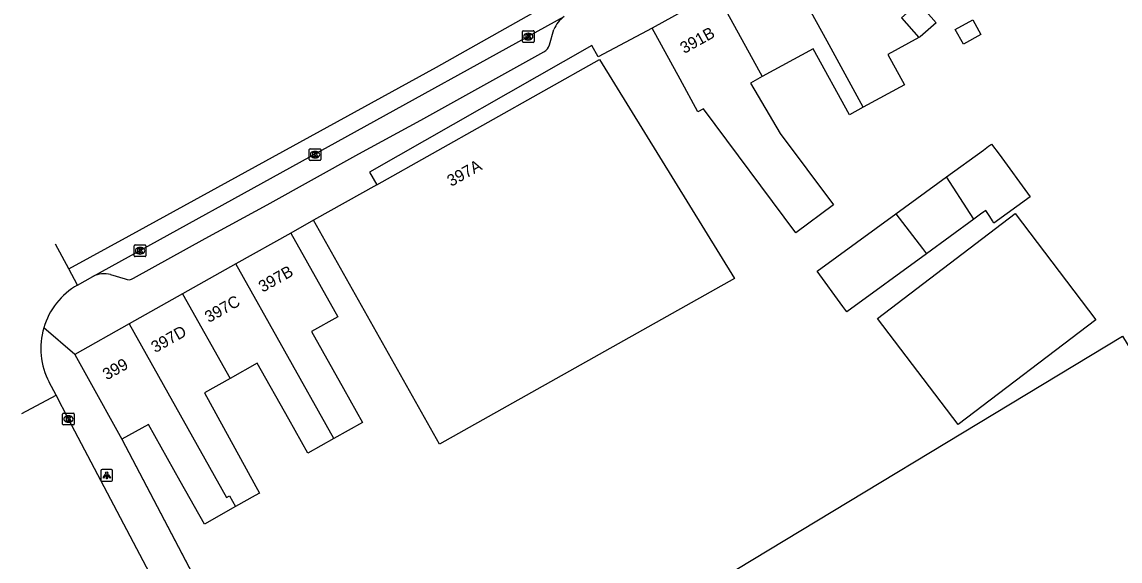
# Model space of a CAD drawing. Extents: x 159822 to 160765, y 380693 to 381634.
# Drawn here: x 159821.7 to 159915.8, y 381400.1 to 381446.3 of the extents above; entities that cross this region are included whole.
import ezdxf

# ---------------------------------------------------------------- set-up
doc = ezdxf.new("R2010")
doc.units = 0
for name, color, linetype in [('IMGEO_Kolk', 7, 'Continuous'), ('IMGEO_Lichtpunt', 7, 'Continuous'), ('IMGEO_Muur', 7, 'Continuous'), ('IMGEO_Pand', 7, 'Continuous'), ('IMGEO_Pand_nummerreeks', 7, 'Continuous'), ('IMGEO_Rijbaan_lokaal_gesloten', 7, 'Continuous'), ('IMGEO_Rijbaan_lokaal_open', 7, 'Continuous'), ('IMGEO_Voetpad_open', 7, 'Continuous')]:
    doc.layers.add(name, color=color, linetype=linetype)

msp = doc.modelspace()

# ---------------------------------------------------------------- linework, layer by layer
at = {"layer": 'IMGEO_Kolk'}
for p, q in [((159864.611, 381444.58), (159864.611, 381445.432)), ((159864.686, 381445.506), (159865.538, 381445.506)), ((159865.099, 381445.286), (159865.124, 381445.286)), ((159865.612, 381445.432), (159865.612, 381444.58)), ((159865.538, 381444.506), (159864.686, 381444.506)), ((159865.122, 381444.726), (159865.097, 381444.726)), ((159846.345, 381434.465), (159846.345, 381435.317)), ((159846.42, 381435.391), (159847.272, 381435.391)), ((159846.833, 381435.171), (159846.858, 381435.171)), ((159847.346, 381435.317), (159847.346, 381434.465)), ((159847.272, 381434.391), (159846.42, 381434.391)), ((159846.856, 381434.611), (159846.831, 381434.611)), ((159831.425, 381427.153), (159832.277, 381427.153)), ((159831.35, 381426.227), (159831.35, 381427.079)), ((159831.861, 381426.373), (159831.836, 381426.373)), ((159831.838, 381426.933), (159831.863, 381426.933)), ((159832.351, 381427.079), (159832.351, 381426.227)), ((159832.277, 381426.153), (159831.425, 381426.153)), ((159825.217, 381411.813), (159825.217, 381412.665)), ((159825.292, 381412.739), (159826.144, 381412.739)), ((159825.705, 381412.519), (159825.73, 381412.519)), ((159826.218, 381412.665), (159826.218, 381411.813)), ((159826.144, 381411.739), (159825.292, 381411.739)), ((159825.728, 381411.959), (159825.703, 381411.959))]:
    msp.add_line(p, q, dxfattribs=at)
for points in [[(159864.611, 381444.58), (159864.611, 381445.432)], [(159864.686, 381445.506), (159865.538, 381445.506)], [(159864.932, 381445.206), (159865.055, 381445.206), (159865.055, 381445.055), (159865.185, 381445.206), (159865.349, 381445.206), (159865.203, 381445.055), (159865.356, 381444.806), (159865.204, 381444.806), (159865.119, 381444.97), (159865.055, 381444.903), (159865.055, 381444.806), (159864.932, 381444.806), (159864.932, 381445.206)], [(159865.612, 381445.432), (159865.612, 381444.58)], [(159865.538, 381444.506), (159864.686, 381444.506)], [(159846.345, 381434.465), (159846.345, 381435.317)], [(159846.42, 381435.391), (159847.272, 381435.391)], [(159846.666, 381435.091), (159846.789, 381435.091), (159846.789, 381434.94), (159846.919, 381435.091), (159847.083, 381435.091), (159846.937, 381434.94), (159847.09, 381434.691), (159846.938, 381434.691), (159846.853, 381434.855), (159846.789, 381434.788), (159846.789, 381434.691), (159846.666, 381434.691), (159846.666, 381435.091)], [(159847.346, 381435.317), (159847.346, 381434.465)], [(159847.272, 381434.391), (159846.42, 381434.391)], [(159831.425, 381427.153), (159832.277, 381427.153)], [(159831.35, 381426.227), (159831.35, 381427.079)], [(159831.671, 381426.853), (159831.794, 381426.853), (159831.794, 381426.702), (159831.924, 381426.853), (159832.088, 381426.853), (159831.942, 381426.702), (159832.095, 381426.453), (159831.943, 381426.453), (159831.858, 381426.617), (159831.794, 381426.55), (159831.794, 381426.453), (159831.671, 381426.453), (159831.671, 381426.853)], [(159832.351, 381427.079), (159832.351, 381426.227)], [(159832.277, 381426.153), (159831.425, 381426.153)], [(159825.217, 381411.813), (159825.217, 381412.665)], [(159825.292, 381412.739), (159826.144, 381412.739)], [(159825.538, 381412.439), (159825.661, 381412.439), (159825.661, 381412.288), (159825.791, 381412.439), (159825.955, 381412.439), (159825.809, 381412.288), (159825.962, 381412.039), (159825.81, 381412.039), (159825.725, 381412.203), (159825.661, 381412.136), (159825.661, 381412.039), (159825.538, 381412.039), (159825.538, 381412.439)], [(159826.218, 381412.665), (159826.218, 381411.813)], [(159826.144, 381411.739), (159825.292, 381411.739)]]:
    msp.add_lwpolyline(points, dxfattribs=at)
for centre, start, end in [((159864.688, 381445.43), 91.55205, 178.44795), ((159864.688, 381445.43), 91.55205, 178.44795), ((159865.536, 381445.43), 1.55205, 88.44795), ((159865.536, 381445.43), 1.55205, 88.44795), ((159864.688, 381444.582), 181.55205, 268.44795), ((159864.688, 381444.582), 181.55205, 268.44795), ((159865.536, 381444.582), 271.55205, 358.44795), ((159865.536, 381444.582), 271.55205, 358.44795), ((159846.422, 381435.315), 91.55205, 178.44795), ((159846.422, 381435.315), 91.55205, 178.44795), ((159847.27, 381435.315), 1.55205, 88.44795), ((159847.27, 381435.315), 1.55205, 88.44795), ((159846.422, 381434.467), 181.55205, 268.44795), ((159846.422, 381434.467), 181.55205, 268.44795), ((159847.27, 381434.467), 271.55205, 358.44795), ((159847.27, 381434.467), 271.55205, 358.44795), ((159831.427, 381427.077), 91.55205, 178.44795), ((159831.427, 381427.077), 91.55205, 178.44795), ((159832.275, 381427.077), 1.55205, 88.44795), ((159832.275, 381427.077), 1.55205, 88.44795), ((159831.427, 381426.229), 181.55205, 268.44795), ((159831.427, 381426.229), 181.55205, 268.44795), ((159832.275, 381426.229), 271.55205, 358.44795), ((159832.275, 381426.229), 271.55205, 358.44795), ((159825.294, 381412.663), 91.55205, 178.44795), ((159825.294, 381412.663), 91.55205, 178.44795), ((159826.142, 381412.663), 1.55205, 88.44795), ((159826.142, 381412.663), 1.55205, 88.44795), ((159825.294, 381411.815), 181.55205, 268.44795), ((159825.294, 381411.815), 181.55205, 268.44795), ((159826.142, 381411.815), 271.55205, 358.44795), ((159826.142, 381411.815), 271.55205, 358.44795)]:
    msp.add_arc(centre, 0.0765, start, end, dxfattribs=at)
for centre, major_axis, ratio, start_param, end_param in [((159865.098, 381445.006), (-0.387, 0.002), 0.722429, 4.712389, 7.853982), ((159865.123, 381445.006), (-0.39, 0.002), 0.717154, 1.570796, 4.712389), ((159846.832, 381434.891), (-0.387, 0.002), 0.722429, 4.712389, 7.853982), ((159846.857, 381434.891), (-0.39, 0.002), 0.717154, 1.570796, 4.712389), ((159831.837, 381426.653), (-0.387, 0.002), 0.722429, 4.712389, 7.853982), ((159831.862, 381426.653), (-0.39, 0.002), 0.717154, 1.570796, 4.712389), ((159825.704, 381412.239), (-0.387, 0.002), 0.722429, 4.712389, 7.853982), ((159825.729, 381412.239), (-0.39, 0.002), 0.717154, 1.570796, 4.712389)]:
    msp.add_ellipse(centre, major_axis=major_axis, ratio=ratio, start_param=start_param, end_param=end_param, dxfattribs=at)
at = {"layer": 'IMGEO_Lichtpunt'}
for p, q in [((159828.504, 381407.813), (159828.504, 381407.006)), ((159828.504, 381407.813), (159828.504, 381407.006)), ((159829.406, 381407.908), (159828.598, 381407.908)), ((159829.406, 381407.908), (159828.598, 381407.908)), ((159829.5, 381407.006), (159829.5, 381407.813)), ((159829.5, 381407.006), (159829.5, 381407.813)), ((159828.598, 381406.912), (159829.406, 381406.912)), ((159828.598, 381406.912), (159829.406, 381406.912))]:
    msp.add_line(p, q, dxfattribs=at)
for points in [[(159828.878, 381407.477), (159828.917, 381407.449), (159828.729, 381407.187), (159828.691, 381407.214), (159828.878, 381407.477)], [(159828.98, 381407.429), (159829.027, 381407.429), (159829.027, 381407.107), (159828.98, 381407.107), (159828.98, 381407.429)], [(159829.09, 381407.449), (159829.128, 381407.476), (159829.315, 381407.214), (159829.276, 381407.186), (159829.09, 381407.449)]]:
    msp.add_lwpolyline(points, dxfattribs=at)
msp.add_circle((159829.003, 381407.611), 0.0994, dxfattribs=at)
for centre, start, end in [((159828.598, 381407.813), 90, 180), ((159828.598, 381407.813), 90, 180), ((159829.406, 381407.813), 0, 90), ((159829.406, 381407.813), 0, 90), ((159828.598, 381407.006), 180, 270), ((159828.598, 381407.006), 180, 270), ((159829.406, 381407.006), 270, 0), ((159829.406, 381407.006), 270, 360)]:
    msp.add_arc(centre, 0.0946, start, end, dxfattribs=at)
at = {"layer": 'IMGEO_Muur'}
msp.add_lwpolyline([(159830.299, 381410.506), (159839.705, 381392.562)], dxfattribs=at)
at = {"layer": 'IMGEO_Pand'}
for points in [[(159893.815, 381438.943), (159890.708, 381444.614), (159886.749, 381451.841)], [(159881.217, 381448.776), (159875.721, 381445.731)], [(159881.217, 381448.776), (159885.161, 381441.575)], [(159897.083, 381446.618), (159898.555, 381447.908), (159900.065, 381446.186), (159898.679, 381444.97), (159898.574, 381444.917)], [(159897.083, 381446.618), (159898.574, 381444.917)], [(159902.399, 381444.344), (159901.7, 381445.604), (159903.192, 381446.432), (159903.891, 381445.172), (159902.399, 381444.344)], [(159885.161, 381441.575), (159884.154, 381441.024), (159886.707, 381436.69), (159891.258, 381430.588), (159888.044, 381428.191), (159880.12, 381438.814), (159879.651, 381438.557), (159878.123, 381441.346), (159875.721, 381445.731)], [(159898.574, 381444.917), (159895.925, 381443.466), (159897.344, 381440.876), (159893.815, 381438.943)], [(159893.815, 381438.943), (159892.623, 381438.29), (159889.516, 381443.961), (159885.161, 381441.575)], [(159852.13, 381432.298), (159871.226, 381443.029), (159882.774, 381424.291), (159857.517, 381410.099), (159846.727, 381429.262)], [(159900.951, 381432.985), (159904.111, 381435.286), (159904.543, 381435.601), (159904.81, 381435.796), (159905.446, 381434.923), (159908.101, 381431.279), (159905.008, 381429.025), (159904.878, 381429.225), (159904.652, 381429.576), (159904.313, 381430.101), (159904.144, 381429.978), (159903.866, 381429.776), (159903.292, 381429.358)], [(159896.617, 381429.827), (159900.951, 381432.985)], [(159903.292, 381429.358), (159902.983, 381429.837), (159900.951, 381432.985)], [(159852.13, 381432.298), (159846.727, 381429.262)], [(159899.229, 381426.398), (159892.398, 381421.421), (159892.063, 381421.881), (159889.859, 381424.905), (159896.617, 381429.827)], [(159913.744, 381420.743), (159901.957, 381411.766), (159895.032, 381420.859), (159906.819, 381429.836), (159913.744, 381420.743)], [(159896.617, 381429.827), (159898.884, 381426.851), (159899.229, 381426.398)], [(159903.292, 381429.358), (159899.229, 381426.398)], [(159844.762, 381428.172), (159840.06, 381425.526)], [(159844.762, 381428.172), (159848.788, 381421.006), (159846.538, 381419.742), (159849.284, 381414.854), (159850.922, 381411.939), (159848.467, 381410.56)], [(159840.06, 381425.526), (159835.492, 381422.956)], [(159848.467, 381410.56), (159840.06, 381425.526)], [(159835.492, 381422.956), (159830.923, 381420.385)], [(159835.492, 381422.956), (159839.564, 381415.707)], [(159830.923, 381420.385), (159826.256, 381417.759)], [(159830.923, 381420.385), (159839.271, 381405.522), (159839.502, 381405.655), (159840.031, 381404.734)], [(159888.162, 381381.468), (159878.875, 381396.888), (159916.025, 381419.326), (159925.649, 381403.516)], [(159826.256, 381417.759), (159827.398, 381415.711), (159830.299, 381410.506)], [(159848.467, 381410.56), (159846.23, 381409.304), (159844.593, 381412.219), (159841.898, 381417.018), (159839.564, 381415.707)], [(159839.564, 381415.707), (159837.382, 381414.481), (159842.077, 381405.884), (159841.728, 381405.688), (159840.031, 381404.734)], [(159840.031, 381404.734), (159837.369, 381403.238), (159835.301, 381406.917), (159832.568, 381411.781), (159830.299, 381410.506)]]:
    msp.add_lwpolyline(points, dxfattribs=at)
at = {"layer": 'IMGEO_Rijbaan_lokaal_gesloten'}
msp.add_lwpolyline([(159825.741, 381425.114), (159830.92, 381427.938), (159857.238, 381442.392), (159881.509, 381456.068), (159898.004, 381465.69), (159907.745, 381471.382), (159914.294, 381475.19), (159926.777, 381482.151), (159943.271, 381491.16), (159954.568, 381497.138), (159968.238, 381504.058), (159981.458, 381511.387), (159987.706, 381515.056)], dxfattribs=at)
at = {"layer": 'IMGEO_Rijbaan_lokaal_open'}
for points in [[(159827.8, 381424.443), (159868.202, 381446.726)], [(159825.741, 381425.114), (159824.612, 381427.213)], [(159826.493, 381423.716), (159825.741, 381425.114)], [(159826.493, 381423.716), (159827.8, 381424.443)], [(159824.671, 381414.27), (159824.061, 381415.403)], [(159821.736, 381412.719), (159821.736, 381412.719), (159824.671, 381414.27)], [(159864.153, 381338.89), (159864.033, 381339.093), (159861.736, 381343.466), (159850.225, 381365.883), (159846.313, 381373.251), (159844.505, 381376.716), (159841.951, 381381.527), (159840.044, 381385.182), (159838.551, 381387.886), (159836.907, 381391.037), (159834.344, 381395.861), (159825.713, 381412.239), (159824.671, 381414.27)]]:
    msp.add_lwpolyline(points, dxfattribs=at)
for centre, radius, start, end in [((159829.616, 381418.287), 6.263, 119.91512, 163.67391), ((159829.608, 381418.291), 6.254, 163.68502, 207.50407)]:
    msp.add_arc(centre, radius, start, end, dxfattribs=at)
at = {"layer": 'IMGEO_Voetpad_open'}
for points in [[(159875.721, 381445.731), (159871.093, 381443.281), (159870.548, 381444.237), (159851.506, 381433.392), (159852.13, 381432.298)], [(159866.938, 381444.286), (159867.316, 381445.611)], [(159831.295, 381424.311), (159837.434, 381427.698), (159842.73, 381430.591), (159850.606, 381434.963), (159855.913, 381437.849), (159866.441, 381443.7)], [(159846.727, 381429.262), (159844.762, 381428.172)], [(159829.333, 381424.611), (159830.579, 381424.247)], [(159826.256, 381417.759), (159823.606, 381420.048)], [(159830.299, 381410.506), (159838.42, 381395.012)]]:
    msp.add_lwpolyline(points, dxfattribs=at)
for centre, radius, start, end in [((159869.598, 381444.707), 2.454, 124.6625, 158.39487), ((159865.959, 381444.613), 1.033, 297.85381, 341.54211), ((159828.776, 381422.617), 2.071, 74.39266, 118.11541), ((159830.888, 381424.824), 0.655, 241.81545, 308.40022)]:
    msp.add_arc(centre, radius, start, end, dxfattribs=at)

# ---------------------------------------------------------------- texts
at = {"layer": 'IMGEO_Pand_nummerreeks'}
for s, rotation, p in [('391B', 28.98818, (159878.468, 381443.504)), ('397A', 29.33343, (159858.507, 381432.119)), ('397B', 29.36569, (159842.357, 381423.055)), ('397C', 29.36569, (159837.743, 381420.459)), ('397D', 29.36569, (159833.154, 381417.876)), ('399', 29.36569, (159828.997, 381415.538))]:
    msp.add_text(s, height=1, rotation=rotation, dxfattribs=at).set_placement(p)

doc.saveas('drawing.dxf')
